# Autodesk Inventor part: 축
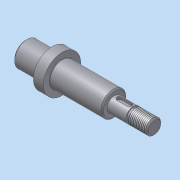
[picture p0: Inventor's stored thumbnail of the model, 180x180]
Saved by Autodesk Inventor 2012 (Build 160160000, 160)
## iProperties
Created: 2015-03
Part Number: 축
Material: 강
Document SubType Name: Modeling
Designer: KYOUNG IL JANG
Density: 1 g/cm^3
CustomPartVersion: 1
Author: KYOUNG IL JANG
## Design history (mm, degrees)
sketch "스케치5"
  geometry: L1 (0, 0)-(103, 0); L2 (0, 0)-(103, 0); L3 (103, 0)-(103, 6); L4 (71, 6)-(71, 10); L5 (71, 10)-(29, 10); L6 (29, 10)-(29, 15); L7 (29, 15)-(21, 15); L8 (21, 15)-(21, 10); L9 (21, 10)-(0, 10); L10 (0, 10)-(0, 0); L11 (86, 6)-(86, 5); L12 (86, 5)-(88, 5); L13 (88, 5)-(88, 6); L14 (103, 6)-(88, 6); L15 (86, 6)-(71, 6)
  constraints: 31 end point, 12 perpendicular, 9 parallel, 1 collinear, 1 horizontal
  dimensions: "d43" = 20 diameter of L9 L1; "d44" = 30 diameter of L7 L1; "d45" = 20 diameter of L5 L2; "d47" = 8 distance of L6.end L7.end; "d48" = 32 distance between parallel lines of L3 L4; "d49" = 42 distance between parallel lines of L4 L6; "d50" = 21 distance of L8.end L9.end; "d52" = 12 diameter of L14 L1; "d53" = 15 distance between parallel lines of L3 L13; "d54" = 2 distance of L11.end L12.end; "d55" = 1 distance between parallel lines of L14 L12
revolve "회전4" sketch "스케치5" stored, may be unused: angle "d51" = 90 deg
feature "스레드6" dims "d56" = 10, "d57" = 0
chamfer "모따기6" distance "d32" = 1; stored, may be unused: second distance "d33" = 0.4, angle "d34" = 45 deg
chamfer "모따기5" distance "d27" = 1; stored, may be unused: second distance "d28" = 0.125, angle "d29" = 45 deg
fillet "모깎기1" dims "d17" = 0.3
fillet "모깎기2" dims "d18" = 0.3
chamfer "모따기3" distance "d19" = 1; stored, may be unused: second distance "d20" = 1, angle "d21" = 45 deg
node "작업 평면1"
sketch "스케치6"
  geometry: L1 (-3.5, 2)-(4.5, 2); L2 (4.5, -2)-(-3.5, -2); L3 (-7.5, 9)-(-7.5, -9) reference; A1 r 2 centre (4.5, 0) between (4.5, -2) and (4.5, 2); A2 r 2 centre (-3.5, 0) between (-3.5, 2) and (-3.5, -2); 1 further point
  constraints: 4 end point, 4 point on circle, 4 tangent, 2 centre point, 1 horizontal, 1 horizontal alignment, 1 parallel
  dimensions: "d59" = 2 distance edge to line of A2 L3; "d60" = 12 dimension on A1 A2; "d61" = 4 distance between parallel lines of L2 L1
extrude "돌출1" cut sketch "스케치6" distance "d62" = 2.3; taper "d63" = 0 deg
node "솔리드1"
node "솔리드2"
other parameters: "d46" = 12
